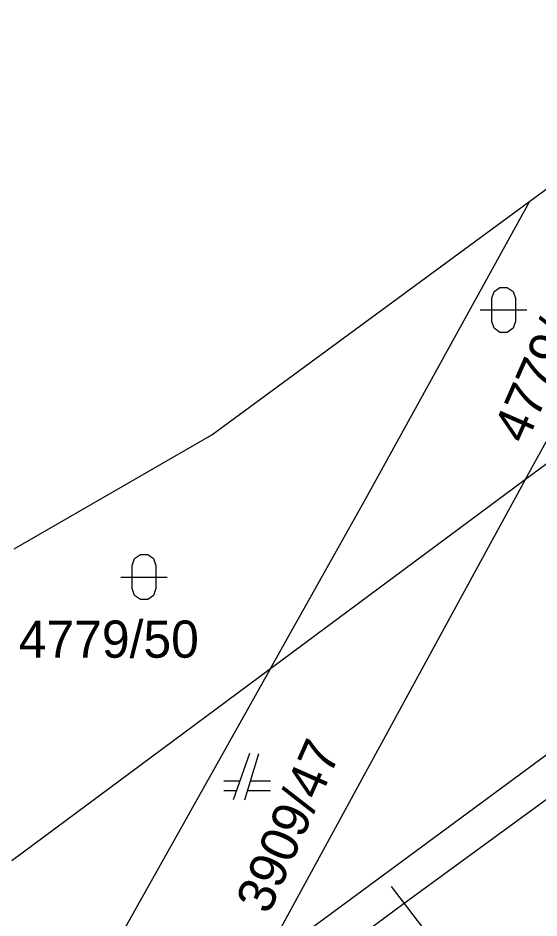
# Model space of a CAD drawing. Extents: x -266179 to -264727, y -1243225 to -1241702.
# Drawn here: x -265316.32 to -265293.95, y -1242905.34 to -1242866.65 of the extents above; entities that cross this region are included whole.
import ezdxf

# ---------------------------------------------------------------- set-up
doc = ezdxf.new("R2010")
doc.units = 0
doc.layers.add('Vrstva 1', color=7, linetype='Continuous')
doc.layers.add('Vrstva 2', color=7, linetype='Continuous')

msp = doc.modelspace()

# ---------------------------------------------------------------- linework, layer by layer
at = {"layer": 'Vrstva 1'}
for p, q in [((-265294.52, -1242886.48), (-265283.64, -1242866.65)), ((-265294.34, -1242874.52), (-265283.64, -1242866.65)), ((-265308, -1242884.57), (-265294.34, -1242874.52)), ((-265301.39, -1242887.33), (-265294.34, -1242874.52)), ((-265294.52, -1242886.48), (-265281.23, -1242876.6)), ((-265316.48, -1242889.47), (-265308, -1242884.57)), ((-265305.47, -1242894.61), (-265294.52, -1242886.48)), ((-265294.52, -1242886.48), (-265296.39, -1242889.88)), ((-265305.47, -1242894.61), (-265301.39, -1242887.33)), ((-265296.39, -1242889.88), (-265305.93, -1242907.41)), ((-265305.47, -1242894.61), (-265317.38, -1242915.83)), ((-265316.59, -1242902.87), (-265305.47, -1242894.61)), ((-265292.9, -1242897.79), (-265305.93, -1242907.41)), ((-265306.38, -1242898.26), (-265307.08, -1242900.26)), ((-265306.58, -1242900.26), (-265305.98, -1242898.26)), ((-265306.8, -1242899.46), (-265307.48, -1242899.46)), ((-265305.48, -1242899.46), (-265306.34, -1242899.46)), ((-265307.48, -1242899.86), (-265306.94, -1242899.86)), ((-265306.46, -1242899.86), (-265305.48, -1242899.86))]:
    msp.add_line(p, q, dxfattribs=at)
for points in [[(-265295.97, -1242878.7), (-265295.87, -1242878.41), (-265295.62, -1242878.23), (-265295.31, -1242878.23), (-265295.06, -1242878.41), (-265294.96, -1242878.7), (-265294.96, -1242879.7), (-265295.06, -1242879.99), (-265295.31, -1242880.17), (-265295.62, -1242880.17), (-265295.87, -1242879.99), (-265295.97, -1242879.7)], [(-265311.41, -1242890.18), (-265311.31, -1242889.89), (-265311.06, -1242889.71), (-265310.75, -1242889.71), (-265310.5, -1242889.89), (-265310.4, -1242890.18), (-265310.4, -1242891.18), (-265310.5, -1242891.47), (-265310.75, -1242891.65), (-265311.06, -1242891.65), (-265311.31, -1242891.47), (-265311.41, -1242891.18)]]:
    msp.add_lwpolyline(points, close=True, dxfattribs=at)
for points in [[(-265296.47, -1242879.2), (-265295.2, -1242879.2), (-265294.47, -1242879.2)], [(-265311.91, -1242890.68), (-265310.64, -1242890.68), (-265309.91, -1242890.68)]]:
    msp.add_lwpolyline(points, dxfattribs=at)
at = {"layer": 'Vrstva 2'}
for p, q in [((-265283.42, -1242892.78), (-265299.74, -1242904.71)), ((-265300.3, -1242903.99), (-265299.74, -1242904.71)), ((-265299.74, -1242904.71), (-265315.61, -1242916.53)), ((-265299.74, -1242904.71), (-265297.18, -1242908.03))]:
    msp.add_line(p, q, dxfattribs=at)

# ---------------------------------------------------------------- texts
at = {"layer": 'Vrstva 1'}
for s, rotation, p in [('4779/49', 66.2912, (-265294.503, -1242885.018)), ('3909/47', 66.1766, (-265305.551, -1242905.231))]:
    msp.add_text(s, height=1.6, rotation=rotation, dxfattribs=at).set_placement(p)
msp.add_text('4779/50', height=1.6, dxfattribs=at).set_placement((-265316.287, -1242894.15))

doc.saveas('drawing.dxf')
